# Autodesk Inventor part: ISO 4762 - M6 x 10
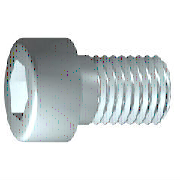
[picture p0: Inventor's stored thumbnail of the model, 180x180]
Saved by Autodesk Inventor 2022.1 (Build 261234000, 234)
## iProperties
Created: 2021-02
Part Number: ISO 4762 - M6 x 10
Material: Acier inoxydable 440C
Description: Vis cylindrique à six pans creux
Document SubType Name: Modeling
Standard: ISO 4762
Designer: Fabian
Standard Revision: Fourth edition 2004-03-01
Standards Organization: ISO
Language: fr-FR
Size Designation: M6 x 10
Categories: <MemberInstance><Categories><Category DisplayName="Visserie" InternalName="e4da775c-781d-43d5-af7c-5136215cf5a6" Mnemonic="FSTN"><Category DisplayName="Vis" Int
Density: 7.75 g/cm^3
Appearance: Semi-poli
IsCustomPart: 0
Author: Fabian
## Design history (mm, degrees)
sketch "Esquisse1"
  geometry: L1 (-1.333, 0)-(10, 0); L2 (10, 0)-(10, 3); L3 (10, 3)-(2.5, 3); L4 (2.5, 3)-(1.886, 3); L5 (1.886, 3)-(0, 3); L6 (0, 3)-(0, 5); L7 (0, 5)-(-6, 5); L8 (-6, 5)-(-6, 2.887); L9 (-6, 2.887)-(-3, 2.887); L10 (-3, 2.887)-(-1.333, 0); L11 (-9.2, 0)-(13.2, 0) reference; L12 (0, -1)-(0, 6) reference; L13 (2.5, 3)-(0, 3)
  constraints: 22 end point, 6 parallel, 2 collinear, 2 perpendicular, 1 horizontal, 1 point on line
  dimensions: "d1" = 7.5 distance from line of L3.end L2 (= GEL); "d2" = 0.61355 distance of L4.end L3.end (computed from GAL); "d3" = 6 distance between parallel lines of L8 L6 (= KOH); "d4" = 3 distance of L8.end L9.end (= INTI); "d5" = 60 deg angle of L10 L1; "d6" = 6 diameter of L3 L1 (= GD); "d7" = 6 diameter of L5 L1 (= BDM); "d8" = 5.7735 diameter of L9 L1 (= 1.1547 x SW); "d9" = 10 diameter of L7 L1 (= KOD); "d26" = 10 distance between parallel lines of L12 L2 (= NLG)
revolve "Corps" sketch "Esquisse1" stored, may be unused: angle "d10" = 90 deg
sketch "Esquisse2"
  geometry: L1 (0, -7)-(0, 7) reference; L2 (-7, 0)-(7, 0) reference; L3 (2.887, 0)-(1.443, -2.5); L4 (1.443, -2.5)-(-1.443, -2.5); L5 (-1.443, -2.5)-(-2.887, 0); L6 (-2.887, 0)-(-1.443, 2.5); L7 (-1.443, 2.5)-(1.443, 2.5); L8 (1.443, 2.5)-(2.887, 0); 2 further points
  constraints: 12 end point, 1 coincident, 1 horizontal alignment, 1 point on line, 12 other
extrude "Rainure" join sketch "Esquisse2" stored distance "d11" = 10; taper "d12" = 0 deg
workplane "Work Plane1"
fillet "Fillet2" dims "d30" = 0.1 (= R)
body "Solid1"
fillet "Congé1" dims "d17" = 0.6 (= RR)
feature "Filetage" dims "d13" = 7.5 (= GEL), "d14" = 0
chamfer "Chanfrein1" distance "d15" = 0.61345 (= -0.5 x SPD + 0.5 x GD); stored, may be unused: second distance "d16" = 0.61345 (= GUL), angle "d27" = 45 deg
other parameters: "GD" = 6 [user parameter; used in 2 equation terms], "NLG" = 10 [user parameter; used in 1 equation term], "GEL" = 7.5 [user parameter; used in 2 equation terms], "KOD" = 10 [user parameter; used in 1 equation term], "KOH" = 6 [user parameter; used in 1 equation term], "INTI" = 3 [user parameter; used in 1 equation term], "GAL" = 0.61345 (= 0.61345 x PTC) [user parameter; used in 1 equation term], "GUL" = 0.61345 (= 0.61345 x PTC) [user parameter; used in 1 equation term], "BDM" = 6 (= NND) [user parameter; used in 1 equation term], "SW" = 5 [user parameter; used in 2 equation terms], "RR" = 0.6 [user parameter; used in 1 equation term], "SPD" = 4.7731 (= NND - 1.2269 x PTC) [user parameter; used in 1 equation term], "d19" = 0, "d28" = 0, "d29" = 0, "R" = 0.1 [user parameter; used in 1 equation term], "TOA" = 30 deg [user parameter], "GD1" = 4.7731 (= THREADDIA - 1.2269 x PTC) [user parameter], "THREADDIA" = 6 [user parameter; used in 1 equation term], "FAWI" = 45 deg [user parameter], "PTC" = 1 [user parameter; used in 5 equation terms], "NND" = 6 [user parameter; used in 2 equation terms], "E0" = 5.775 (= 1.155 x SW) [user parameter]
